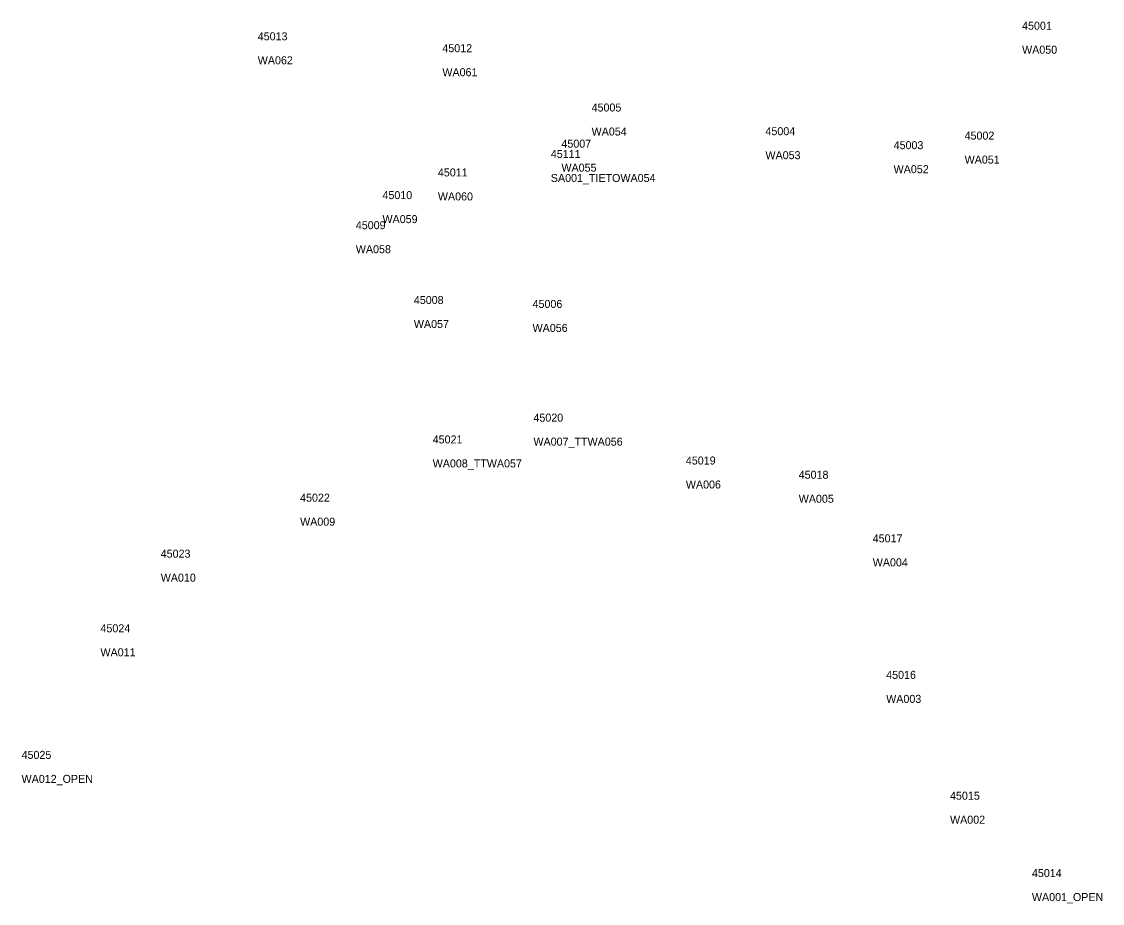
# Model space of a CAD drawing. Extents: x 1503676 to 1665494, y 654328 to 989038.
# Drawn here: x 1543229.6 to 1543567.3, y 655182 to 655457.6 of the extents above; entities that cross this region are included whole.
import ezdxf

# ---------------------------------------------------------------- set-up
doc = ezdxf.new("R2010")
doc.units = 0
for name, color, linetype in [('Level 14', 7, 'Continuous'), ('Level 17', 7, 'Continuous'), ('Level 18', 7, 'Continuous'), ('Level 19', 7, 'Continuous')]:
    doc.layers.add(name, color=color, linetype=linetype)

msp = doc.modelspace()

# ---------------------------------------------------------------- texts
at = {"layer": 'Level 14'}
for s, p in [('45001', (1543542.21, 655455.02)), ('45013', (1543303.4, 655451.71)), ('45012', (1543361.08, 655447.99)), ('45005', (1543407.71, 655429.46)), ('45004', (1543462.03, 655422.06)), ('45002', (1543524.25, 655420.68)), ('45007', (1543398.28, 655418.16)), ('45003', (1543502.07, 655417.69)), ('45011', (1543359.68, 655409.17)), ('45010', (1543342.37, 655402.08)), ('45009', (1543334.04, 655392.68)), ('45008', (1543352.17, 655369.3)), ('45006', (1543389.26, 655368.07)), ('45020', (1543389.54, 655332.53)), ('45021', (1543358.06, 655325.73)), ('45019', (1543437.16, 655319.14)), ('45018', (1543472.42, 655314.69)), ('45022', (1543316.63, 655307.52)), ('45017', (1543495.55, 655294.81)), ('45023', (1543273.08, 655290.03)), ('45024', (1543254.26, 655266.7)), ('45016', (1543499.75, 655252.15)), ('45025', (1543229.61, 655227.14)), ('45015', (1543519.7, 655214.38)), ('45014', (1543545.28, 655190.2))]:
    msp.add_text(s, height=2.5, dxfattribs=at).set_placement(p)
at = {"layer": 'Level 17'}
for s, p in [('WA050', (1543542.21, 655447.52)), ('WA062', (1543303.4, 655444.21)), ('WA061', (1543361.08, 655440.49)), ('WA054', (1543407.71, 655421.96)), ('WA053', (1543462.03, 655414.56)), ('WA051', (1543524.25, 655413.18)), ('WA055', (1543398.28, 655410.66)), ('WA052', (1543502.07, 655410.19)), ('WA060', (1543359.68, 655401.67)), ('WA059', (1543342.37, 655394.58)), ('WA058', (1543334.04, 655385.18)), ('WA057', (1543352.17, 655361.8)), ('WA056', (1543389.26, 655360.57)), ('WA007_TTWA056', (1543389.54, 655325.03)), ('WA008_TTWA057', (1543358.06, 655318.23)), ('WA006', (1543437.16, 655311.64)), ('WA005', (1543472.42, 655307.19)), ('WA009', (1543316.63, 655300.02)), ('WA004', (1543495.55, 655287.31)), ('WA010', (1543273.08, 655282.53)), ('WA011', (1543254.26, 655259.2)), ('WA003', (1543499.75, 655244.65)), ('WA012_OPEN', (1543229.61, 655219.64)), ('WA002', (1543519.7, 655206.88)), ('WA001_OPEN', (1543545.28, 655182.7))]:
    msp.add_text(s, height=2.5, dxfattribs=at).set_placement(p)
at = {"layer": 'Level 18'}
msp.add_text('SA001_TIETOWA054', height=2.5, dxfattribs=at).set_placement((1543394.97, 655407.44))
at = {"layer": 'Level 19'}
msp.add_text('45111', height=2.5, dxfattribs=at).set_placement((1543394.97, 655414.94))

doc.saveas('drawing.dxf')
